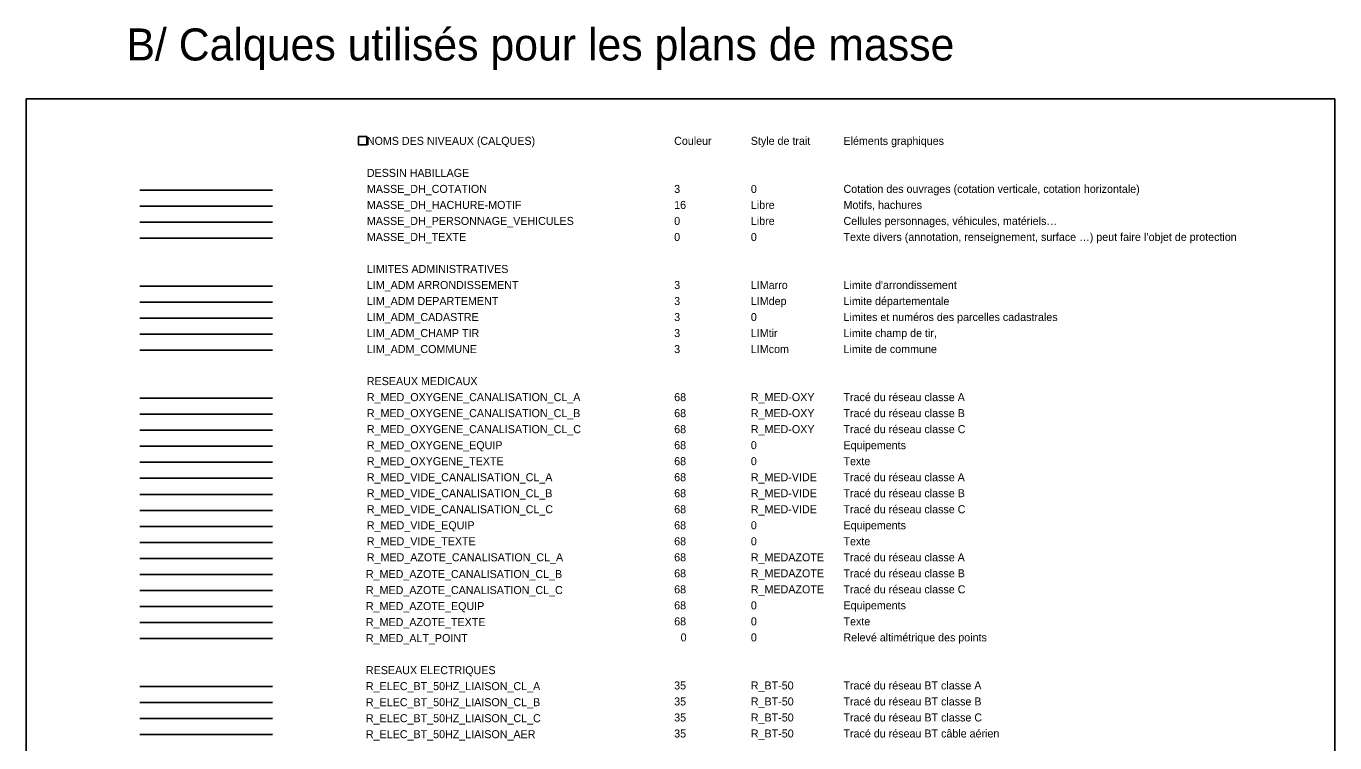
# Model space of a CAD drawing. Extents: x -60 to 214, y -380 to -21.
# Drawn here: x 33.1 to 114.8, y -65.9 to -21.2 of the extents above; entities that cross this region are included whole.
import ezdxf

# ---------------------------------------------------------------- set-up
doc = ezdxf.new("R2010")
doc.units = 0
for name, color, linetype in [('Default', 7, 'Continuous'), ('DH_TEXTE', 7, 'Continuous'), ('Lib01', 7, 'Continuous'), ('LIM_ADM ARRONDISSEMENT', 7, 'Continuous'), ('LIM_ADM DEPARTEMENT', 7, 'Continuous'), ('LIM_ADM_CADASTRE', 7, 'Continuous'), ('LIM_ADM_CHAMP TIR', 7, 'Continuous'), ('LIM_ADM_COMMUNE', 7, 'Continuous'), ('MASSE_DH_COTATION', 7, 'Continuous'), ('MASSE_DH_HACHURE-MOTIF', 7, 'Continuous'), ('MASSE_DH_PERSONNAGE_VEHICULES', 7, 'Continuous'), ('MASSE_DH_TEXTE', 7, 'Continuous'), ('R_ELEC_BT_50HZ_LIAISON_CL_A', 7, 'Continuous'), ('R_ELEC_BT_50HZ_LIAISON_CL_B', 7, 'Continuous'), ('R_ELEC_BT_50HZ_LIAISON_CL_C', 7, 'Continuous'), ('R_MED_ALT_POINT', 7, 'Continuous'), ('R_MED_AZOTE_CANALISATION_CL_A', 7, 'Continuous'), ('R_MED_AZOTE_CANALISATION_CL_B', 7, 'Continuous'), ('R_MED_AZOTE_CANALISATION_CL_C', 7, 'Continuous'), ('R_MED_AZOTE_EQUIP', 7, 'Continuous'), ('R_MED_AZOTE_TEXTE', 7, 'Continuous'), ('R_MED_OXYGENE_CANALISATION_CL_A', 7, 'Continuous'), ('R_MED_OXYGENE_CANALISATION_CL_B', 7, 'Continuous'), ('R_MED_OXYGENE_CANALISATION_CL_C', 7, 'Continuous'), ('R_MED_OXYGENE_EQUIP', 7, 'Continuous'), ('R_MED_OXYGENE_TEXTE', 7, 'Continuous'), ('R_MED_VIDE_CANALISATION_CL_A', 7, 'Continuous'), ('R_MED_VIDE_CANALISATION_CL_B', 7, 'Continuous'), ('R_MED_VIDE_CANALISATION_CL_C', 7, 'Continuous'), ('R_MED_VIDE_EQUIP', 7, 'Continuous'), ('R_MED_VIDE_TEXTE', 7, 'Continuous')]:
    doc.layers.add(name, color=color, linetype=linetype)

msp = doc.modelspace()

# ---------------------------------------------------------------- linework, layer by layer
at = {"layer": 'Default'}
msp.add_line((40.178, -65.429), (48.457, -65.429), dxfattribs=at)
msp.add_lwpolyline([(114.838, -25.727), (33.073, -25.727), (33.073, -380.216), (114.838, -380.216)], close=True, dxfattribs=at)
at = {"layer": 'Lib01'}
msp.add_lwpolyline([(53.847, -28.096), (54.36, -28.096), (54.36, -28.61), (53.847, -28.61)], close=True, dxfattribs=at)
at = {"layer": 'LIM_ADM ARRONDISSEMENT'}
msp.add_line((48.457, -37.429), (40.178, -37.429), dxfattribs=at)
at = {"layer": 'LIM_ADM DEPARTEMENT'}
msp.add_line((40.178, -38.429), (48.457, -38.429), dxfattribs=at)
at = {"layer": 'LIM_ADM_CADASTRE'}
msp.add_line((40.178, -39.429), (48.457, -39.429), dxfattribs=at)
at = {"layer": 'LIM_ADM_CHAMP TIR'}
msp.add_line((40.178, -40.429), (48.457, -40.429), dxfattribs=at)
at = {"layer": 'LIM_ADM_COMMUNE'}
msp.add_line((40.178, -41.429), (48.457, -41.429), dxfattribs=at)
at = {"layer": 'MASSE_DH_COTATION'}
msp.add_line((40.178, -31.429), (48.457, -31.429), dxfattribs=at)
at = {"layer": 'MASSE_DH_HACHURE-MOTIF'}
msp.add_line((40.178, -32.429), (48.457, -32.429), dxfattribs=at)
at = {"layer": 'MASSE_DH_PERSONNAGE_VEHICULES'}
msp.add_line((40.178, -33.429), (48.457, -33.429), dxfattribs=at)
at = {"layer": 'MASSE_DH_TEXTE'}
msp.add_line((40.178, -34.429), (48.457, -34.429), dxfattribs=at)
at = {"layer": 'R_ELEC_BT_50HZ_LIAISON_CL_A'}
msp.add_line((40.178, -62.429), (48.457, -62.429), dxfattribs=at)
at = {"layer": 'R_ELEC_BT_50HZ_LIAISON_CL_B'}
msp.add_line((40.178, -63.429), (48.457, -63.429), dxfattribs=at)
at = {"layer": 'R_ELEC_BT_50HZ_LIAISON_CL_C'}
msp.add_line((40.178, -64.429), (48.457, -64.429), dxfattribs=at)
at = {"layer": 'R_MED_ALT_POINT'}
msp.add_line((40.178, -59.429), (48.457, -59.429), dxfattribs=at)
at = {"layer": 'R_MED_AZOTE_CANALISATION_CL_A'}
msp.add_line((40.178, -54.429), (48.457, -54.429), dxfattribs=at)
at = {"layer": 'R_MED_AZOTE_CANALISATION_CL_B'}
msp.add_line((40.178, -55.429), (48.457, -55.429), dxfattribs=at)
at = {"layer": 'R_MED_AZOTE_CANALISATION_CL_C'}
msp.add_line((40.178, -56.429), (48.457, -56.429), dxfattribs=at)
at = {"layer": 'R_MED_AZOTE_EQUIP'}
msp.add_line((40.178, -57.429), (48.457, -57.429), dxfattribs=at)
at = {"layer": 'R_MED_AZOTE_TEXTE'}
msp.add_line((40.178, -58.429), (48.457, -58.429), dxfattribs=at)
at = {"layer": 'R_MED_OXYGENE_CANALISATION_CL_A'}
msp.add_line((40.178, -44.429), (48.457, -44.429), dxfattribs=at)
at = {"layer": 'R_MED_OXYGENE_CANALISATION_CL_B'}
msp.add_line((40.178, -45.429), (48.457, -45.429), dxfattribs=at)
at = {"layer": 'R_MED_OXYGENE_CANALISATION_CL_C'}
msp.add_line((40.178, -46.429), (48.457, -46.429), dxfattribs=at)
at = {"layer": 'R_MED_OXYGENE_EQUIP'}
msp.add_line((40.178, -47.429), (48.457, -47.429), dxfattribs=at)
at = {"layer": 'R_MED_OXYGENE_TEXTE'}
msp.add_line((40.178, -48.429), (48.457, -48.429), dxfattribs=at)
at = {"layer": 'R_MED_VIDE_CANALISATION_CL_A'}
msp.add_line((40.178, -49.429), (48.457, -49.429), dxfattribs=at)
at = {"layer": 'R_MED_VIDE_CANALISATION_CL_B'}
msp.add_line((40.178, -50.429), (48.457, -50.429), dxfattribs=at)
at = {"layer": 'R_MED_VIDE_CANALISATION_CL_C'}
msp.add_line((40.178, -51.429), (48.457, -51.429), dxfattribs=at)
at = {"layer": 'R_MED_VIDE_EQUIP'}
msp.add_line((40.178, -52.429), (48.457, -52.429), dxfattribs=at)
at = {"layer": 'R_MED_VIDE_TEXTE'}
msp.add_line((40.178, -53.429), (48.457, -53.429), dxfattribs=at)

# ---------------------------------------------------------------- texts
at = {"layer": 'Default'}
msp.add_text('B/ Calques utilisés pour les plans de masse', height=2, dxfattribs=at).set_placement((39.335, -23.342))
at = {"layer": 'DH_TEXTE'}
for s, p in [('NOMS DES NIVEAUX (CALQUES) ', (54.36, -28.61)), ('Couleur ', (73.559, -28.61)), ('Style de trait ', (78.348, -28.61)), ('Eléments graphiques ', (84.138, -28.61)), ('DESSIN HABILLAGE ', (54.36, -30.61)), ('LIMITES ADMINISTRATIVES', (54.36, -36.61)), ('RESEAUX MEDICAUX ', (54.36, -43.61)), ('0', (73.964, -59.611)), ('RESEAUX ELECTRIQUES ', (54.301, -61.655)), ('R_ELEC_BT_50HZ_LIAISON_AER ', (54.301, -65.655)), ('35 ', (73.561, -65.61)), ('R_BT-50 ', (78.351, -65.61)), ('Tracé du réseau BT câble aérien ', (84.14, -65.61))]:
    msp.add_text(s, height=0.5, dxfattribs=at).set_placement(p)
at = {"layer": 'LIM_ADM ARRONDISSEMENT'}
for s, p in [('LIM_ADM ARRONDISSEMENT  ', (54.36, -37.61)), ('3 ', (73.561, -37.61)), ('LIMarro  ', (78.351, -37.61)), ("Limite d'arrondissement ", (84.14, -37.61))]:
    msp.add_text(s, height=0.5, dxfattribs=at).set_placement(p)
at = {"layer": 'LIM_ADM DEPARTEMENT'}
for s, p in [('LIM_ADM DEPARTEMENT  ', (54.36, -38.61)), ('3 ', (73.561, -38.61)), ('LIMdep  ', (78.351, -38.61)), ('Limite départementale ', (84.14, -38.61))]:
    msp.add_text(s, height=0.5, dxfattribs=at).set_placement(p)
at = {"layer": 'LIM_ADM_CADASTRE'}
for s, p in [('LIM_ADM_CADASTRE ', (54.36, -39.61)), ('3 ', (73.561, -39.61)), ('0 ', (78.351, -39.61)), ('Limites et numéros des parcelles cadastrales ', (84.14, -39.61))]:
    msp.add_text(s, height=0.5, dxfattribs=at).set_placement(p)
at = {"layer": 'LIM_ADM_CHAMP TIR'}
for s, p in [('LIM_ADM_CHAMP TIR  ', (54.36, -40.61)), ('3 ', (73.561, -40.61)), ('LIMtir  ', (78.351, -40.61)), ('Limite champ de tir,  ', (84.14, -40.61))]:
    msp.add_text(s, height=0.5, dxfattribs=at).set_placement(p)
at = {"layer": 'LIM_ADM_COMMUNE'}
for s, p in [('LIM_ADM_COMMUNE ', (54.36, -41.61)), ('3 ', (73.561, -41.61)), ('LIMcom  ', (78.351, -41.61)), ('Limite de commune ', (84.14, -41.61))]:
    msp.add_text(s, height=0.5, dxfattribs=at).set_placement(p)
at = {"layer": 'MASSE_DH_COTATION'}
for s, p in [('MASSE_DH_COTATION  ', (54.36, -31.61)), ('3 ', (73.561, -31.61)), ('0 ', (78.351, -31.61)), ('Cotation des ouvrages (cotation verticale, cotation horizontale) ', (84.14, -31.61))]:
    msp.add_text(s, height=0.5, dxfattribs=at).set_placement(p)
at = {"layer": 'MASSE_DH_HACHURE-MOTIF'}
for s, p in [('MASSE_DH_HACHURE-MOTIF ', (54.36, -32.61)), ('16 ', (73.561, -32.61)), ('Libre ', (78.351, -32.61)), ('Motifs, hachures ', (84.14, -32.61))]:
    msp.add_text(s, height=0.5, dxfattribs=at).set_placement(p)
at = {"layer": 'MASSE_DH_PERSONNAGE_VEHICULES'}
for s, p in [('MASSE_DH_PERSONNAGE_VEHICULES ', (54.36, -33.61)), ('0 ', (73.561, -33.61)), ('Libre ', (78.351, -33.61)), ('Cellules personnages, véhicules, matériels…', (84.14, -33.61))]:
    msp.add_text(s, height=0.5, dxfattribs=at).set_placement(p)
at = {"layer": 'MASSE_DH_TEXTE'}
for s, p in [('MASSE_DH_TEXTE  ', (54.36, -34.61)), ('0 ', (73.561, -34.61)), ('0 ', (78.351, -34.61)), ('Texte divers (annotation, renseignement, surface …) peut faire l’objet de protection ', (84.14, -34.61))]:
    msp.add_text(s, height=0.5, dxfattribs=at).set_placement(p)
at = {"layer": 'R_ELEC_BT_50HZ_LIAISON_CL_A'}
for s, p in [('35 ', (73.559, -62.61)), ('R_BT-50 ', (78.348, -62.61)), ('Tracé du réseau BT classe A ', (84.138, -62.61)), ('R_ELEC_BT_50HZ_LIAISON_CL_A ', (54.301, -62.655))]:
    msp.add_text(s, height=0.5, dxfattribs=at).set_placement(p)
at = {"layer": 'R_ELEC_BT_50HZ_LIAISON_CL_B'}
for s, p in [('R_ELEC_BT_50HZ_LIAISON_CL_B ', (54.301, -63.655)), ('35 ', (73.561, -63.61)), ('R_BT-50 ', (78.351, -63.61)), ('Tracé du réseau BT classe B ', (84.14, -63.61))]:
    msp.add_text(s, height=0.5, dxfattribs=at).set_placement(p)
at = {"layer": 'R_ELEC_BT_50HZ_LIAISON_CL_C'}
for s, p in [('R_ELEC_BT_50HZ_LIAISON_CL_C ', (54.301, -64.655)), ('35 ', (73.561, -64.61)), ('R_BT-50 ', (78.351, -64.61)), ('Tracé du réseau BT classe C ', (84.14, -64.61))]:
    msp.add_text(s, height=0.5, dxfattribs=at).set_placement(p)
at = {"layer": 'R_MED_ALT_POINT'}
for s, p in [('R_MED_ALT_POINT  ', (54.301, -59.655)), ('0 ', (78.351, -59.61)), ('Relevé altimétrique des points ', (84.14, -59.61))]:
    msp.add_text(s, height=0.5, dxfattribs=at).set_placement(p)
at = {"layer": 'R_MED_AZOTE_CANALISATION_CL_A'}
for s, p in [('R_MED_AZOTE_CANALISATION_CL_A ', (54.36, -54.61)), ('68 ', (73.561, -54.61)), ('R_MEDAZOTE ', (78.351, -54.61)), ('Tracé du réseau classe A ', (84.14, -54.61))]:
    msp.add_text(s, height=0.5, dxfattribs=at).set_placement(p)
at = {"layer": 'R_MED_AZOTE_CANALISATION_CL_B'}
for s, p in [('R_MED_AZOTE_CANALISATION_CL_B ', (54.301, -55.655)), ('68 ', (73.561, -55.61)), ('R_MEDAZOTE ', (78.351, -55.61)), ('Tracé du réseau classe B ', (84.14, -55.61))]:
    msp.add_text(s, height=0.5, dxfattribs=at).set_placement(p)
at = {"layer": 'R_MED_AZOTE_CANALISATION_CL_C'}
for s, p in [('R_MED_AZOTE_CANALISATION_CL_C ', (54.301, -56.655)), ('68 ', (73.561, -56.61)), ('R_MEDAZOTE ', (78.351, -56.61)), ('Tracé du réseau classe C ', (84.14, -56.61))]:
    msp.add_text(s, height=0.5, dxfattribs=at).set_placement(p)
at = {"layer": 'R_MED_AZOTE_EQUIP'}
for s, p in [('R_MED_AZOTE_EQUIP ', (54.301, -57.655)), ('68 ', (73.561, -57.61)), ('0 ', (78.351, -57.61)), ('Equipements ', (84.14, -57.61))]:
    msp.add_text(s, height=0.5, dxfattribs=at).set_placement(p)
at = {"layer": 'R_MED_AZOTE_TEXTE'}
for s, p in [('R_MED_AZOTE_TEXTE ', (54.301, -58.655)), ('68', (73.561, -58.61)), ('0 ', (78.351, -58.61)), ('Texte ', (84.14, -58.61))]:
    msp.add_text(s, height=0.5, dxfattribs=at).set_placement(p)
at = {"layer": 'R_MED_OXYGENE_CANALISATION_CL_A'}
for s, p in [('R_MED_OXYGENE_CANALISATION_CL_A ', (54.36, -44.61)), ('68 ', (73.561, -44.61)), ('R_MED-OXY ', (78.351, -44.61)), ('Tracé du réseau classe A ', (84.14, -44.61))]:
    msp.add_text(s, height=0.5, dxfattribs=at).set_placement(p)
at = {"layer": 'R_MED_OXYGENE_CANALISATION_CL_B'}
for s, p in [('R_MED_OXYGENE_CANALISATION_CL_B ', (54.36, -45.61)), ('68 ', (73.561, -45.61)), ('R_MED-OXY ', (78.351, -45.61)), ('Tracé du réseau classe B ', (84.14, -45.61))]:
    msp.add_text(s, height=0.5, dxfattribs=at).set_placement(p)
at = {"layer": 'R_MED_OXYGENE_CANALISATION_CL_C'}
for s, p in [('R_MED_OXYGENE_CANALISATION_CL_C ', (54.36, -46.61)), ('68 ', (73.561, -46.61)), ('R_MED-OXY ', (78.351, -46.61)), ('Tracé du réseau classe C ', (84.14, -46.61))]:
    msp.add_text(s, height=0.5, dxfattribs=at).set_placement(p)
at = {"layer": 'R_MED_OXYGENE_EQUIP'}
for s, p in [('R_MED_OXYGENE_EQUIP ', (54.36, -47.61)), ('68 ', (73.561, -47.61)), ('0 ', (78.351, -47.61)), ('Equipements ', (84.14, -47.61))]:
    msp.add_text(s, height=0.5, dxfattribs=at).set_placement(p)
at = {"layer": 'R_MED_OXYGENE_TEXTE'}
for s, p in [('R_MED_OXYGENE_TEXTE ', (54.36, -48.61)), ('68 ', (73.561, -48.61)), ('0 ', (78.351, -48.61)), ('Texte ', (84.14, -48.61))]:
    msp.add_text(s, height=0.5, dxfattribs=at).set_placement(p)
at = {"layer": 'R_MED_VIDE_CANALISATION_CL_A'}
for s, p in [('R_MED_VIDE_CANALISATION_CL_A ', (54.36, -49.61)), ('68 ', (73.561, -49.61)), ('R_MED-VIDE ', (78.351, -49.61)), ('Tracé du réseau classe A ', (84.14, -49.61))]:
    msp.add_text(s, height=0.5, dxfattribs=at).set_placement(p)
at = {"layer": 'R_MED_VIDE_CANALISATION_CL_B'}
for s, p in [('R_MED_VIDE_CANALISATION_CL_B ', (54.36, -50.61)), ('68 ', (73.561, -50.61)), ('R_MED-VIDE ', (78.351, -50.61)), ('Tracé du réseau classe B ', (84.14, -50.61))]:
    msp.add_text(s, height=0.5, dxfattribs=at).set_placement(p)
at = {"layer": 'R_MED_VIDE_CANALISATION_CL_C'}
for s, p in [('R_MED_VIDE_CANALISATION_CL_C ', (54.36, -51.61)), ('68 ', (73.561, -51.61)), ('R_MED-VIDE ', (78.351, -51.61)), ('Tracé du réseau classe C ', (84.14, -51.61))]:
    msp.add_text(s, height=0.5, dxfattribs=at).set_placement(p)
at = {"layer": 'R_MED_VIDE_EQUIP'}
for s, p in [('R_MED_VIDE_EQUIP ', (54.36, -52.61)), ('68 ', (73.561, -52.61)), ('0 ', (78.351, -52.61)), ('Equipements ', (84.14, -52.61))]:
    msp.add_text(s, height=0.5, dxfattribs=at).set_placement(p)
at = {"layer": 'R_MED_VIDE_TEXTE'}
for s, p in [('R_MED_VIDE_TEXTE ', (54.36, -53.61)), ('68 ', (73.561, -53.61)), ('0 ', (78.351, -53.61)), ('Texte ', (84.14, -53.61))]:
    msp.add_text(s, height=0.5, dxfattribs=at).set_placement(p)

doc.saveas('drawing.dxf')
